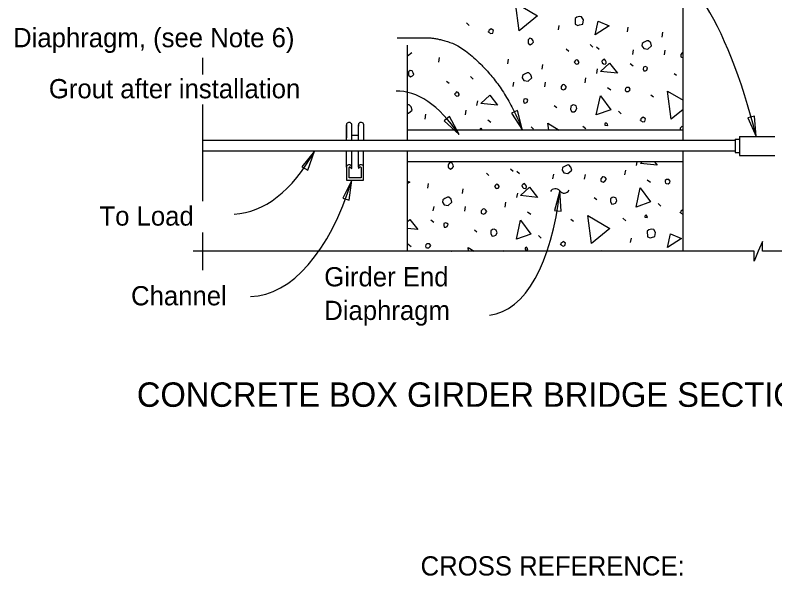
# Model space of a CAD drawing. Extents: x 0 to 30.8, y 0 to 21.2.
# Drawn here: x 19.54 to 25.52, y 9.83 to 14.24 of the extents above; entities that cross this region are included whole.
import ezdxf

# ---------------------------------------------------------------- set-up
doc = ezdxf.new("R2010")
doc.units = 0
for name, color, linetype in [('Dimension', 7, 'Continuous'), ('Lighting', 7, 'Continuous'), ('Miscellaneous', 7, 'Continuous'), ('SupstrConc', 7, 'Continuous'), ('TextStructures', 7, 'Continuous')]:
    doc.layers.add(name, color=color, linetype=linetype)

msp = doc.modelspace()

# ---------------------------------------------------------------- linework, layer by layer
at = {"layer": 'Dimension'}
for points in [[(21.0171, 13.7764), (21.0171, 13.9071)], [(21.0171, 12.7801), (21.0171, 13.539)], [(21.0171, 12.2366), (21.0171, 12.5343)], [(28.7417, 12.3859), (25.4201, 12.3859), (25.4201, 12.4634), (25.3864, 12.3859), (25.3526, 12.3084), (25.3526, 12.3859), (20.9396, 12.3859)]]:
    msp.add_lwpolyline(points, dxfattribs=at)
for points in [[(23.5307, 13.3387), (23.4923, 13.4924), (23.4438, 13.4711)], [(25.3692, 13.2888), (25.3556, 13.4466), (25.3044, 13.4333)], [(23.032, 13.3041), (22.9572, 13.4437), (22.9154, 13.4113)], [(21.8954, 13.1721), (21.7956, 13.0491), (21.8417, 13.0231)], [(22.1885, 12.9445), (22.1168, 12.8032), (22.1673, 12.7875)], [(23.8248, 12.8597), (23.7822, 12.7071), (23.8348, 12.7016)]]:
    msp.add_lwpolyline(points, close=True, dxfattribs=at)
for centre, start, end in [((23.7891, 12.8321), 38.18218, 149.9094), ((23.8594, 12.8873), 218.18218, 329.9094)]:
    msp.add_arc(centre, 0.0447, start, end, dxfattribs=at)
for centre, major_axis, ratio, start_param, end_param in [((24.3864, 11.0659), (-0.0172, -3.681), 0.331804, 2.220726, 3.141608), ((22.6905, 10.4552), (0.1544, -3.1879), 0.324138, 2.660287, 3.141582), ((21.1524, 15.0448), (-0.1111, 2.3674), 0.464296, 3.141604, 3.778402), ((21.3152, 14.2357), (-0.0751, 2.2066), 0.468341, 3.141584, 4.071496), ((23.081, 13.5038), (-0.1909, 1.6213), 0.453794, 3.141619, 4.251067)]:
    msp.add_ellipse(centre, major_axis=major_axis, ratio=ratio, start_param=start_param, end_param=end_param, dxfattribs=at)
msp.add_open_spline([(22.5455, 14.0636), (22.7215, 14.0636), (22.8523, 14.0636), (23.0786, 13.9881), (23.4105, 13.6359), (23.5307, 13.3387)], degree=2, dxfattribs=at)
at = {"layer": 'Lighting'}
for p, q in [((22.188, 13.3848), (22.1858, 13.3887)), ((22.2423, 13.3887), (22.2402, 13.3848)), ((22.1464, 13.2554), (22.1464, 13.3804)), ((22.1464, 13.3804), (22.1464, 13.2779)), ((22.188, 13.3687), (22.188, 13.3848)), ((22.188, 13.2554), (22.188, 13.3804)), ((22.2402, 13.3848), (22.2402, 13.3687)), ((22.2402, 13.2554), (22.2402, 13.3804)), ((22.2818, 13.2554), (22.2818, 13.3804)), ((22.2402, 13.2965), (22.188, 13.2965)), ((25.2387, 13.2888), (25.5161, 13.2888)), ((25.2387, 13.2887), (25.2387, 13.1389)), ((25.2053, 13.2554), (21.0171, 13.2554)), ((25.2053, 13.2658), (25.2053, 13.1617)), ((25.2053, 13.2658), (25.2387, 13.2658)), ((25.2053, 13.1721), (21.0171, 13.1721)), ((22.1463, 13.0471), (22.1463, 13.1721)), ((22.1879, 13.0471), (22.1879, 13.1721)), ((22.2401, 13.0471), (22.2401, 13.1721)), ((22.2817, 13.0471), (22.2817, 13.1721)), ((25.2053, 13.1617), (25.2387, 13.1617)), ((25.2387, 13.1389), (25.5161, 13.1389)), ((22.1463, 13.0471), (22.1463, 12.9445)), ((22.1671, 12.9631), (22.1671, 13.0428)), ((22.176, 13.0461), (22.1879, 13.0354)), ((22.1879, 13.0514), (22.1858, 13.0553)), ((22.1879, 13.0354), (22.1879, 13.0514)), ((22.2423, 13.0553), (22.2401, 13.0514)), ((22.2401, 13.0514), (22.2401, 13.0354)), ((22.2401, 13.0354), (22.2521, 13.0461)), ((22.2609, 13.0428), (22.2609, 12.9631)), ((22.2817, 12.9445), (22.2817, 13.0471)), ((22.1463, 12.9445), (22.2817, 12.9445)), ((22.2609, 12.9631), (22.1671, 12.9631))]:
    msp.add_line(p, q, dxfattribs=at)
for centre, major_axis, start_param, end_param in [((22.1672, 13.3804), (-0.0208, 0), 3.598509, 6.283184), ((22.261, 13.3804), (0.0208, 0), 0.000002, 2.684677), ((22.1671, 13.0471), (-0.0208, 0), 3.598509, 6.283184), ((22.1723, 13.0428), (-0.0052, 0), 3.926991, 6.283185), ((22.2609, 13.0471), (0.0208, 0), 0.000002, 2.684677), ((22.2557, 13.0428), (0.0052, 0), 6.283185, 8.63938)]:
    msp.add_ellipse(centre, major_axis=major_axis, ratio=0.8951, start_param=start_param, end_param=end_param, dxfattribs=at)
at = {"layer": 'Miscellaneous'}
for p, q in [((23.0902, 14.1801), (23.1112, 14.1598)), ((23.814, 14.1255), (23.8201, 14.1608)), ((24.3564, 14.1104), (24.3618, 14.1481)), ((24.6288, 14.0695), (24.6342, 14.1072)), ((24.0646, 14.0115), (24.0855, 13.9912)), ((24.1134, 13.9935), (24.1343, 13.9733)), ((23.8747, 13.9762), (23.895, 13.9583)), ((24.3988, 13.9328), (24.4049, 13.9681)), ((24.6481, 13.9297), (24.6535, 13.9674)), ((22.8722, 13.8732), (22.8783, 13.9085)), ((23.4146, 13.8581), (23.4201, 13.8957)), ((23.687, 13.8172), (23.6924, 13.8548)), ((24.1151, 13.7843), (24.1211, 13.8196)), ((24.3788, 13.8628), (24.4021, 13.8431)), ((23.1228, 13.7591), (23.1437, 13.7389)), ((24.0235, 13.7106), (24.029, 13.7483)), ((24.7233, 13.7843), (24.743, 13.7688)), ((22.933, 13.7238), (22.9533, 13.706)), ((23.457, 13.6805), (23.4631, 13.7158)), ((23.7063, 13.6774), (23.7118, 13.7151)), ((24.1994, 13.6723), (24.2252, 13.6534)), ((23.1733, 13.532), (23.1794, 13.5673)), ((24.5406, 13.6162), (24.5609, 13.5984)), ((23.7815, 13.5319), (23.8012, 13.5165)), ((22.7645, 13.425), (22.77, 13.4627)), ((23.0818, 13.4583), (23.0872, 13.496)), ((24.2856, 13.4858), (24.3066, 13.4655)), ((23.2577, 13.42), (23.2834, 13.401)), ((24.794, 13.3387), (22.6274, 13.3387)), ((23.5988, 13.3639), (23.6191, 13.346)), ((24.0062, 13.3695), (24.0296, 13.3499)), ((24.794, 13.0888), (22.6274, 13.0888)), ((24.429, 13.0595), (24.434, 13.0888)), ((23.4367, 13.0343), (23.4577, 13.014)), ((23.2469, 12.9989), (23.2672, 12.9811)), ((23.4855, 13.0163), (23.5065, 12.996)), ((23.7709, 12.9556), (23.777, 12.9909)), ((24.0202, 12.9525), (24.0257, 12.9902)), ((24.3374, 12.9857), (24.3429, 13.0234)), ((22.7868, 12.8808), (22.7922, 12.9185)), ((24.5133, 12.9475), (24.5391, 12.9285)), ((23.0591, 12.8399), (23.0646, 12.8776)), ((23.4872, 12.8071), (23.4933, 12.8424)), ((24.0955, 12.807), (24.1151, 12.7916)), ((22.8292, 12.7033), (22.8352, 12.7385)), ((23.0785, 12.7002), (23.0839, 12.7379)), ((23.3957, 12.7334), (23.4011, 12.7711)), ((24.5996, 12.7609), (24.6205, 12.7407)), ((23.5716, 12.6951), (23.5974, 12.6762)), ((22.8091, 12.6332), (22.8325, 12.6136)), ((23.9127, 12.639), (23.933, 12.6212)), ((24.3201, 12.6446), (24.3435, 12.625)), ((23.1537, 12.5547), (23.1733, 12.5392)), ((23.6578, 12.5086), (23.6787, 12.4883)), ((22.6298, 12.4428), (22.6556, 12.4238)), ((24.3816, 12.454), (24.3876, 12.4893)), ((22.9709, 12.3867), (22.9717, 12.386)), ((23.3784, 12.3923), (23.3859, 12.386))]:
    msp.add_line(p, q, dxfattribs=at)
for points in [[(23.5055, 14.1179), (23.4775, 14.3382), (23.6496, 14.2368), (23.5055, 14.1179)], [(23.9453, 14.2151), (23.9466, 14.1714), (23.9674, 14.1615), (23.9795, 14.1647), (24.0061, 14.1718), (24.0104, 14.204), (23.996, 14.2287), (23.9772, 14.2314), (23.9579, 14.2262), (23.9453, 14.2151)], [(24.1039, 14.0867), (24.127, 14.1939), (24.2143, 14.1577), (24.1039, 14.0867)], [(23.2649, 14.1078), (23.2833, 14.0972), (23.2977, 14.1011), (23.3029, 14.1206), (23.2839, 14.1336), (23.2755, 14.1262), (23.2665, 14.1212), (23.2649, 14.1078), (23.2636, 14.1126)], [(23.5753, 14.0409), (23.575, 14.0227), (23.5916, 14.009), (23.6072, 14.0184), (23.6173, 14.0288), (23.6141, 14.0409), (23.6047, 14.0565), (23.5883, 14.0599), (23.5758, 14.0488), (23.5753, 14.0409)], [(24.471, 14.0014), (24.4847, 13.9791), (24.517, 13.9748), (24.5462, 14.0008), (24.5398, 14.0249), (24.5225, 14.041), (24.5098, 14.0402), (24.4894, 14.0296), (24.4737, 14.0202), (24.471, 14.0014)], [(22.6595, 13.9446), (22.6274, 13.9181)], [(24.7766, 13.9331), (24.7763, 13.9149), (24.794, 13.9067)], [(24.794, 13.9478), (24.7933, 13.948), (24.7885, 13.9467), (24.7766, 13.9331)], [(23.939, 13.8717), (23.9531, 13.8574), (23.9683, 13.8589), (23.976, 13.8687), (23.9747, 13.8735), (23.966, 13.8867), (23.9544, 13.8914), (23.9467, 13.8816), (23.939, 13.8717)], [(24.1445, 13.8), (24.215, 13.8655), (24.2776, 13.7865), (24.1445, 13.8)], [(24.158, 13.8657), (24.1678, 13.858), (24.1812, 13.8564), (24.1895, 13.8638), (24.1894, 13.8741), (24.1837, 13.8855), (24.1756, 13.8963), (24.1625, 13.8876), (24.1541, 13.8802), (24.158, 13.8657)], [(22.6335, 13.7885), (22.6332, 13.7703), (22.6498, 13.7567), (22.6654, 13.766), (22.6756, 13.7765), (22.6723, 13.7886), (22.663, 13.8042), (22.6465, 13.8075), (22.634, 13.7964), (22.6335, 13.7885)], [(24.4814, 13.8178), (24.4853, 13.8033), (24.498, 13.8041), (24.5094, 13.8098), (24.5152, 13.8268), (24.5084, 13.8328), (24.4968, 13.8374), (24.4823, 13.8336), (24.4814, 13.8178)], [(23.5293, 13.749), (23.543, 13.7268), (23.5752, 13.7225), (23.6045, 13.7485), (23.598, 13.7726), (23.5807, 13.7887), (23.568, 13.7879), (23.5476, 13.7772), (23.532, 13.7679), (23.5293, 13.749)], [(23.8348, 13.6808), (23.8345, 13.6626), (23.8523, 13.6544), (23.8661, 13.6607), (23.8773, 13.6766), (23.8693, 13.6874), (23.8625, 13.6934), (23.8516, 13.6956), (23.8467, 13.6943), (23.8348, 13.6808)], [(22.9972, 13.6194), (23.0114, 13.6051), (23.0265, 13.6065), (23.0342, 13.6164), (23.0329, 13.6212), (23.0242, 13.6344), (23.0126, 13.639), (23.0049, 13.6292), (22.9972, 13.6194)], [(24.3412, 13.6456), (24.3473, 13.6421), (24.3631, 13.6411), (24.3756, 13.6523), (24.3785, 13.6608), (24.3698, 13.674), (24.3492, 13.6737), (24.3408, 13.6662), (24.3386, 13.6553), (24.3412, 13.6456)], [(24.7009, 13.4237), (24.6729, 13.6439), (24.794, 13.5726)], [(23.2027, 13.5476), (23.2732, 13.6131), (23.3358, 13.5341), (23.2027, 13.5476)], [(23.5396, 13.5654), (23.5435, 13.5509), (23.5562, 13.5518), (23.5676, 13.5574), (23.5734, 13.5745), (23.5667, 13.5804), (23.5551, 13.5851), (23.5406, 13.5812), (23.5396, 13.5654)], [(24.1121, 13.4574), (24.1441, 13.6084), (24.2254, 13.4981), (24.1121, 13.4574)], [(22.6274, 13.4709), (22.6334, 13.4701), (22.6627, 13.4961), (22.6562, 13.5203), (22.639, 13.5363), (22.6274, 13.5356)], [(23.9109, 13.5226), (23.9094, 13.4989), (23.9195, 13.4809), (23.937, 13.483), (23.9484, 13.4886), (23.959, 13.507), (23.9532, 13.5287), (23.9355, 13.5369), (23.9234, 13.5337), (23.9109, 13.5226)], [(24.794, 13.5005), (24.7009, 13.4237)], [(23.7379, 13.3387), (23.7311, 13.3916), (23.8209, 13.3387)], [(24.1801, 13.3773), (24.2014, 13.3752), (24.1988, 13.3849), (24.1907, 13.3957), (24.18, 13.3876), (24.1801, 13.3773)], [(24.4603, 13.4135), (24.4787, 13.4029), (24.4932, 13.4068), (24.4983, 13.4263), (24.4793, 13.4393), (24.4709, 13.4319), (24.4619, 13.4269), (24.4603, 13.4135), (24.459, 13.4184)], [(23.1987, 13.3387), (23.2023, 13.356), (23.2151, 13.3387)], [(24.7707, 13.3466), (24.7706, 13.3387)], [(24.794, 13.3635), (24.7837, 13.3656), (24.7712, 13.3545), (24.7707, 13.3466)], [(24.4584, 13.0751), (24.4732, 13.0888)], [(24.5699, 13.0888), (24.5915, 13.0616), (24.4584, 13.0751)], [(22.9474, 13.0636), (22.9471, 13.0454), (22.9637, 13.0318), (22.9793, 13.0411), (22.9895, 13.0516), (22.9862, 13.0637), (22.9769, 13.0793), (22.9604, 13.0827), (22.9479, 13.0715), (22.9474, 13.0636)], [(23.8432, 13.0241), (23.8569, 13.0019), (23.8891, 12.9976), (23.9184, 13.0236), (23.9119, 13.0477), (23.8947, 13.0638), (23.8819, 13.063), (23.8615, 13.0523), (23.8459, 13.043), (23.8432, 13.0241)], [(24.1487, 12.9559), (24.1484, 12.9377), (24.1662, 12.9295), (24.18, 12.9358), (24.1913, 12.9518), (24.1832, 12.9625), (24.1764, 12.9685), (24.1655, 12.9707), (24.1606, 12.9694), (24.1487, 12.9559)], [(22.6273, 12.9353), (22.6447, 12.9282), (22.6273, 12.917)], [(23.3111, 12.8945), (23.3253, 12.8802), (23.3404, 12.8817), (23.3481, 12.8915), (23.3468, 12.8963), (23.3381, 12.9095), (23.3265, 12.9142), (23.3188, 12.9043), (23.3111, 12.8945)], [(23.5301, 12.8885), (23.5399, 12.8808), (23.5533, 12.8792), (23.5617, 12.8866), (23.5615, 12.8969), (23.5559, 12.9083), (23.5478, 12.9191), (23.5346, 12.9104), (23.5262, 12.903), (23.5301, 12.8885)], [(24.6551, 12.9207), (24.6612, 12.9172), (24.677, 12.9163), (24.6895, 12.9274), (24.6924, 12.9359), (24.6837, 12.9491), (24.6631, 12.9488), (24.6547, 12.9414), (24.6525, 12.9304), (24.6551, 12.9207)], [(23.5167, 12.8228), (23.5871, 12.8882), (23.6497, 12.8092), (23.5167, 12.8228)], [(24.426, 12.7325), (24.458, 12.8835), (24.5393, 12.7733), (24.426, 12.7325)], [(22.9014, 12.7718), (22.9151, 12.7496), (22.9473, 12.7453), (22.9766, 12.7712), (22.9701, 12.7954), (22.9529, 12.8115), (22.9402, 12.8106), (22.9197, 12.8), (22.9041, 12.7906), (22.9014, 12.7718)], [(24.2248, 12.7977), (24.2234, 12.774), (24.2334, 12.756), (24.2509, 12.7581), (24.2623, 12.7637), (24.2729, 12.7821), (24.2671, 12.8039), (24.2494, 12.812), (24.2373, 12.8088), (24.2248, 12.7977)], [(23.207, 12.7035), (23.2067, 12.6853), (23.2244, 12.6772), (23.2382, 12.6835), (23.2495, 12.6994), (23.2414, 12.7102), (23.2346, 12.7161), (23.2237, 12.7184), (23.2189, 12.7171), (23.207, 12.7035)], [(24.4941, 12.6524), (24.5153, 12.6504), (24.5127, 12.66), (24.5047, 12.6708), (24.4939, 12.6627), (24.4941, 12.6524)], [(24.794, 12.7139), (24.7932, 12.7145), (24.7848, 12.707), (24.7758, 12.702), (24.7742, 12.6887), (24.7729, 12.6935)], [(24.7742, 12.6887), (24.7926, 12.6781), (24.794, 12.6785)], [(22.6273, 12.6192), (22.6453, 12.6359), (22.7079, 12.5569), (22.6273, 12.5651)], [(23.4842, 12.4802), (23.5162, 12.6311), (23.5975, 12.5209), (23.4842, 12.4802)], [(24.073, 12.4464), (24.0451, 12.6667), (24.2172, 12.5653), (24.073, 12.4464)], [(22.9118, 12.5882), (22.9156, 12.5737), (22.9284, 12.5745), (22.9398, 12.5802), (22.9456, 12.5973), (22.9388, 12.6032), (22.9272, 12.6079), (22.9127, 12.604), (22.9118, 12.5882)], [(23.283, 12.5453), (23.2816, 12.5217), (23.2916, 12.5036), (23.3091, 12.5057), (23.3206, 12.5114), (23.3312, 12.5298), (23.3253, 12.5515), (23.3076, 12.5597), (23.2956, 12.5565), (23.283, 12.5453)], [(24.5129, 12.5436), (24.5142, 12.4999), (24.535, 12.49), (24.5471, 12.4932), (24.5736, 12.5003), (24.5779, 12.5325), (24.5636, 12.5572), (24.5447, 12.5599), (24.5254, 12.5547), (24.5129, 12.5436)], [(24.6715, 12.4153), (24.6945, 12.5224), (24.7819, 12.4863), (24.6715, 12.4153)], [(22.7715, 12.416), (22.7777, 12.4125), (22.7934, 12.4116), (22.806, 12.4227), (22.8089, 12.4312), (22.8002, 12.4444), (22.7796, 12.4441), (22.7712, 12.4367), (22.7689, 12.4257), (22.7715, 12.416)], [(23.8324, 12.4363), (23.8508, 12.4257), (23.8653, 12.4296), (23.8704, 12.4491), (23.8514, 12.4621), (23.843, 12.4547), (23.834, 12.4497), (23.8324, 12.4363), (23.8311, 12.4412)], [(23.1069, 12.386), (23.1033, 12.4144), (23.1514, 12.386)], [(23.5523, 12.4001), (23.5735, 12.398), (23.5709, 12.4077), (23.5629, 12.4184), (23.5521, 12.4104), (23.5523, 12.4001)], [(24.1675, 12.386), (24.1559, 12.3884), (24.1532, 12.386)]]:
    msp.add_lwpolyline(points, dxfattribs=at)
at = {"layer": 'SupstrConc'}
for p, q in [((24.794, 13.2554), (24.794, 16.8413)), ((22.6273, 13.2554), (22.6273, 14.007)), ((22.6273, 12.386), (22.6273, 13.1721)), ((24.794, 12.386), (24.794, 13.1721))]:
    msp.add_line(p, q, dxfattribs=at)

# ---------------------------------------------------------------- texts
at = {"layer": 'Dimension'}
for s, p in [('Diaphragm, (see Note 6)', (19.5237, 13.9895)), ('Girder End', (21.9715, 12.1093)), ('Diaphragm', (21.9715, 11.8453)), ('CROSS REFERENCE:', (22.7296, 9.8363))]:
    msp.add_text(s, height=0.1512, dxfattribs=at).set_placement(p)
at = {"layer": 'TextStructures'}
for s, height, p in [('Grout after installation', 0.1512, (19.8051, 13.5882)), ('To Load', 0.1512, (20.2032, 12.5871)), ('Channel', 0.1512, (20.4517, 11.9602)), ('CONCRETE BOX GIRDER BRIDGE SECTION THRU END BENTS', 0.192, (20.4974, 11.1625))]:
    msp.add_text(s, height=height, dxfattribs=at).set_placement(p)

doc.saveas('drawing.dxf')
